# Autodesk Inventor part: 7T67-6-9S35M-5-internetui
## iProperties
Created: 2010-02
Part Number: 7T67-6-9S35M-5-internetui
Document SubType Name: Modeling
Designer: Darius
Author: Darius
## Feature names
1. Base1
